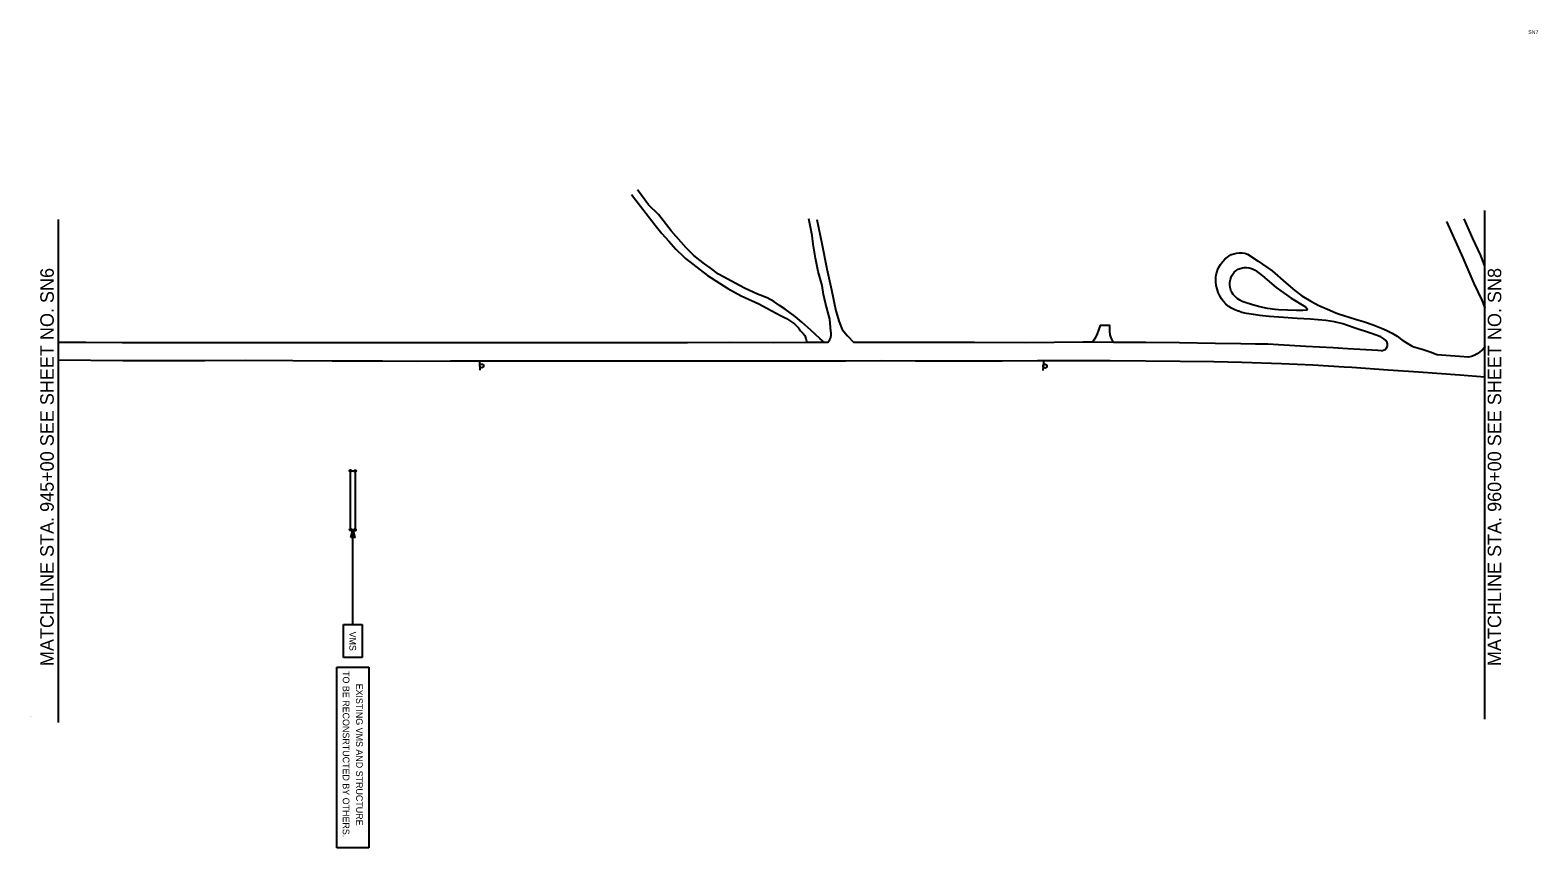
# Model space of a CAD drawing. Extents: x 1738744 to 1740329, y 1163330 to 1164190.
import ezdxf

# ---------------------------------------------------------------- set-up
doc = ezdxf.new("R2010")
doc.units = 0
for name, color, linetype in [('Default', 7, 'Continuous'), ('RD_EX_Driveway', 7, 'Continuous'), ('RD_EX_Road', 7, 'Continuous'), ('RD_SHT_MatchLine', 7, 'Continuous'), ('RD_SHT_TX', 7, 'Continuous'), ('SN_P_Signs', 7, 'Continuous')]:
    doc.layers.add(name, color=color, linetype=linetype)

msp = doc.modelspace()

# ---------------------------------------------------------------- linework, layer by layer
at = {"layer": 'RD_EX_Driveway'}
for points in [[(1739376.2, 1164017.1), (1739401, 1163985), (1739408, 1163976.3), (1739415.3, 1163968), (1739422.9, 1163959.8), (1739430.8, 1163952), (1739432.9, 1163950), (1739456.1, 1163931.9), (1739477.5, 1163918.3), (1739491.4, 1163910.8), (1739510, 1163902.2), (1739523, 1163895.2), (1739533.6, 1163889.6), (1739539, 1163886.8), (1739547.4, 1163881.2), (1739551.6, 1163876.9), (1739553.8, 1163873.8), (1739556.8, 1163871.2), (1739558.3, 1163868.9), (1739559.6, 1163865.8), (1739560.6, 1163861.5)], [(1739579.2, 1163861.6), (1739574.3, 1163865.7), (1739569.7, 1163870.1), (1739564.8, 1163874.6), (1739555.1, 1163883.1), (1739548.1, 1163888.9), (1739537.9, 1163896.8), (1739531.8, 1163900.4), (1739525.7, 1163904.6), (1739518.8, 1163908.5), (1739508.8, 1163912.5), (1739495, 1163918.6), (1739476.8, 1163928.4), (1739467.7, 1163933.6), (1739458.8, 1163940.2), (1739452.8, 1163944.3), (1739447, 1163948.8), (1739441.5, 1163953.6), (1739436.2, 1163958.6), (1739433.8, 1163961.1), (1739417.7, 1163979.1), (1739404.6, 1163996.2), (1739394.1, 1164006.4), (1739382.5, 1164022.1)], [(1739582.6, 1163861.6), (1739584.8, 1163864.8), (1739585.6, 1163867), (1739586, 1163869.3), (1739586.1, 1163871.7), (1739585.9, 1163873.1), (1739584.7, 1163886), (1739580.1, 1163902.8), (1739578.2, 1163912.2), (1739576.6, 1163921.4), (1739572.6, 1163936.3), (1739569.8, 1163950.3), (1739567.3, 1163965), (1739566, 1163974.3), (1739562.6, 1163991.5)], [(1739570.9, 1163990.8), (1739576.2, 1163965.7), (1739581.6, 1163938.9), (1739586.3, 1163917), (1739590.9, 1163895), (1739594.4, 1163883.5), (1739597.8, 1163875.2), (1739603.2, 1163868.6), (1739609.8, 1163861.6)], [(1740164.9, 1163852.8), (1740168.8, 1163854.4), (1740170.3, 1163855.9), (1740171.1, 1163857.8), (1740171.2, 1163859.7), (1740170.7, 1163861.7), (1740169.5, 1163863.6), (1740167.3, 1163865.6), (1740164, 1163867.5), (1740154.2, 1163871.2), (1740136, 1163877.2), (1740124.2, 1163881.1), (1740115.3, 1163883.4), (1740106.2, 1163884.7), (1740090.3, 1163886.1), (1740076.1, 1163887), (1740056.8, 1163888.4), (1740046.8, 1163889.1), (1740036.8, 1163890), (1740030.1, 1163890.9), (1740023, 1163892.1), (1740018.1, 1163893.3), (1740014.8, 1163894.4), (1740014, 1163894.7), (1740010.5, 1163896), (1740007.2, 1163897.6), (1740004.2, 1163899.6), (1740001.3, 1163901.9), (1739998.7, 1163904.6), (1739996.7, 1163907.4), (1739994.7, 1163910.7), (1739993.1, 1163914.2), (1739991.9, 1163917.9), (1739991.1, 1163921.7), (1739990.6, 1163925.5), (1739990.6, 1163929.3), (1739990.7, 1163930.9), (1739991, 1163932.3), (1739991.4, 1163934.3), (1739992.4, 1163937.3), (1739992.5, 1163937.6), (1739993.9, 1163940.8), (1739995.6, 1163943.8), (1739997.7, 1163946.6), (1740000.1, 1163949.2), (1740002.8, 1163951.4), (1740005.7, 1163953.3), (1740006.9, 1163954), (1740007.2, 1163954.1), (1740009.6, 1163955), (1740012.4, 1163955.7), (1740015.3, 1163956), (1740018.2, 1163955.9), (1740021.1, 1163955.4), (1740023.9, 1163954.6), (1740035.1, 1163947), (1740049.8, 1163937.1), (1740064.3, 1163924.3), (1740073.7, 1163916.4), (1740081, 1163910.6), (1740090.4, 1163905), (1740099.1, 1163900.6), (1740108, 1163896.5), (1740117, 1163892.8), (1740119.6, 1163891.8), (1740137.7, 1163886.3), (1740146.9, 1163883.5), (1740156, 1163880.3), (1740164.9, 1163876.7), (1740170.4, 1163874.2), (1740176, 1163871.4), (1740181.3, 1163868.2), (1740181.3, 1163868.1), (1740186.4, 1163864.4), (1740191.7, 1163861), (1740197.2, 1163857.9), (1740198.9, 1163857.1), (1740207.5, 1163854.6), (1740216, 1163851.7), (1740224.1, 1163848.5), (1740224.1, 1163848.5)], [(1740032, 1163937.5), (1740039.7, 1163931.7), (1740054.2, 1163919.6), (1740069.7, 1163908.2), (1740084.9, 1163899), (1740087.2, 1163896.5), (1740086.3, 1163895.6), (1740082.2, 1163895.4), (1740075.5, 1163895.2), (1740056.6, 1163895.9), (1740053, 1163896.3), (1740045, 1163897.5), (1740037, 1163899.2), (1740029.2, 1163901.2), (1740021.4, 1163903.6), (1740018.5, 1163904.6), (1740015.8, 1163906), (1740013.2, 1163907.8), (1740010.9, 1163909.9), (1740008.9, 1163912.2), (1740007.7, 1163914), (1740006.5, 1163916.6), (1740005.8, 1163919.3), (1740005.4, 1163922.1), (1740005.5, 1163924.9), (1740005.9, 1163927.7), (1740006.7, 1163930.4), (1740007.2, 1163931.5), (1740008.4, 1163933.6), (1740010, 1163935.6), (1740011.9, 1163937.2), (1740014, 1163938.6), (1740016.3, 1163939.6), (1740018.8, 1163940.3), (1740020.5, 1163940.5), (1740023.1, 1163940.5), (1740025.7, 1163940.2), (1740028.2, 1163939.5), (1740030.5, 1163938.4), (1740032, 1163937.5)], [(1739883, 1163861.7), (1739880.6, 1163866.4), (1739879.7, 1163869.7), (1739879.2, 1163873.4), (1739879.3, 1163879.4), (1739869, 1163879.5), (1739866, 1163870.6), (1739864.2, 1163867), (1739862.3, 1163864.1), (1739860.8, 1163861.8)]]:
    msp.add_lwpolyline(points, dxfattribs=at)
at = {"layer": 'RD_EX_Road'}
for points in [[(1740273.7, 1163942), (1740269.2, 1163953.2), (1740260.8, 1163971.1), (1740251.7, 1163991.7)], [(1740233.2, 1163988.7), (1740250.5, 1163950.5), (1740262.1, 1163923.6), (1740270.5, 1163906), (1740273.7, 1163898.2)], [(1739582.6, 1163861.6), (1739579.2, 1163861.6), (1739570.3, 1163861.6), (1739560.6, 1163861.5), (1739525, 1163861.4), (1739479.5, 1163861.6), (1739434.9, 1163861.4), (1739394.9, 1163861.4), (1739373.2, 1163861.4), (1739325.9, 1163861.3), (1739285, 1163861.2), (1739247, 1163861.1), (1739205.2, 1163861.3), (1739147.4, 1163861.2), (1739086.9, 1163861.1), (1739037.9, 1163861.1), (1739001, 1163861.4), (1738957.6, 1163861.4), (1738911.8, 1163861.3), (1738877.2, 1163861.4), (1738840.5, 1163861.4), (1738802.3, 1163861.5), (1738773.7, 1163861.6)], [(1740164.8, 1163852.8), (1740161, 1163853.2), (1740129.6, 1163855.1), (1740114.2, 1163855.9), (1740085.4, 1163857.3), (1740056.7, 1163859.1), (1740056.7, 1163859.1), (1740045.2, 1163859.7), (1740033.7, 1163859.9), (1740032.4, 1163859.9), (1740016.8, 1163860.2), (1739989.9, 1163860.7), (1739952.3, 1163861.2), (1739917.2, 1163861.6), (1739891.6, 1163861.7), (1739883, 1163861.7), (1739860.8, 1163861.8), (1739850.7, 1163861.8), (1739790.6, 1163861.4), (1739737, 1163861.5), (1739710.2, 1163861.5), (1739667.2, 1163861.5), (1739609.9, 1163861.6)], [(1740273.7, 1163857.3), (1740273.6, 1163857), (1740271.3, 1163854.3), (1740270.5, 1163853.5), (1740268.1, 1163851.4), (1740265.4, 1163849.6), (1740262.5, 1163848.1), (1740259.5, 1163847), (1740256.4, 1163846.3), (1740256.3, 1163846.3), (1740227.9, 1163848.3), (1740224.1, 1163848.5)], [(1740273.7, 1163825.3), (1740247.1, 1163827.2), (1740203.7, 1163830.3), (1740172, 1163832.4), (1740133.5, 1163835.3), (1740125.5, 1163835.8), (1740092.7, 1163837.8), (1740059.8, 1163839.3), (1740018, 1163840.6), (1739988.7, 1163841.4), (1739953.3, 1163841.6), (1739917.1, 1163842.1), (1739879.5, 1163842.2), (1739845.1, 1163842.2), (1739803, 1163842.3), (1739766, 1163842), (1739708.9, 1163842.1), (1739674.9, 1163842.1), (1739639, 1163842.2), (1739601.6, 1163842.1), (1739566.5, 1163842.1), (1739529.7, 1163842.1), (1739480.9, 1163842.1), (1739439.9, 1163842.1), (1739405.8, 1163842), (1739367.2, 1163841.9), (1739343.7, 1163842.1), (1739306.1, 1163842.1), (1739266.6, 1163842.1), (1739222.4, 1163842), (1739185.9, 1163842.1), (1739151.5, 1163841.8), (1739114.4, 1163841.9), (1739076.4, 1163842), (1739061.4, 1163842.1), (1739019.9, 1163842.2), (1738970.3, 1163842.6), (1738927.5, 1163842.3), (1738889.6, 1163842.5), (1738841.3, 1163842.5), (1738773.7, 1163843)]]:
    msp.add_lwpolyline(points, dxfattribs=at)
at = {"layer": 'RD_SHT_MatchLine'}
for points in [[(1738773.7, 1163461.9), (1738773.7, 1163744), (1738773.7, 1163991)], [(1740273.7, 1163465.6), (1740273.7, 1163744), (1740273.7, 1164000.3)]]:
    msp.add_lwpolyline(points, dxfattribs=at)
at = {"layer": 'SN_P_Signs'}
for p, q in [((1739216.4, 1163841.4), (1739216.8, 1163832.4)), ((1739809.3, 1163841.3), (1739808.7, 1163832.3)), ((1739079.6, 1163726.2), (1739081.4, 1163727.2)), ((1739080, 1163727.6), (1739081, 1163725.8)), ((1739084.6, 1163726), (1739086.3, 1163727)), ((1739085, 1163727.4), (1739085.9, 1163725.6)), ((1739079.9, 1163664.4), (1739081.6, 1163665.3)), ((1739080.2, 1163665.7), (1739081.2, 1163664)), ((1739083.1, 1163565.2), (1739083.1, 1163664.7)), ((1739084.6, 1163664.2), (1739086.3, 1163665.1)), ((1739085, 1163665.5), (1739085.9, 1163663.8)), ((1739073.3, 1163530.2), (1739073.3, 1163565.2)), ((1739073.3, 1163565.2), (1739092.9, 1163565.2)), ((1739092.9, 1163565.2), (1739092.9, 1163530.2)), ((1739066.3, 1163330.2), (1739066.3, 1163520.2)), ((1739066.3, 1163520.2), (1739099.9, 1163520.2)), ((1739092.9, 1163530.2), (1739073.3, 1163530.2)), ((1739099.9, 1163520.2), (1739099.9, 1163330.2)), ((1739099.9, 1163330.2), (1739066.3, 1163330.2))]:
    msp.add_line(p, q, dxfattribs=at)
for points in [[(1739080.2, 1163725.7), (1739080.1, 1163725.8), (1739079.9, 1163725.9), (1739079.8, 1163726), (1739079.7, 1163726.1), (1739079.6, 1163726.2), (1739079.5, 1163726.4), (1739079.5, 1163726.6), (1739079.5, 1163726.7), (1739079.5, 1163726.9), (1739079.6, 1163727), (1739079.7, 1163727.2), (1739079.8, 1163727.3), (1739079.9, 1163727.5), (1739080, 1163727.5), (1739080.2, 1163727.6), (1739080.3, 1163727.7), (1739080.5, 1163727.7), (1739080.7, 1163727.7), (1739080.8, 1163727.6)], [(1739080.8, 1163727.6), (1739080.9, 1163727.6), (1739081.1, 1163727.5), (1739081.2, 1163727.4), (1739081.3, 1163727.3), (1739081.4, 1163727.1), (1739081.5, 1163727), (1739081.5, 1163726.8), (1739081.5, 1163726.6), (1739081.5, 1163726.5), (1739081.4, 1163726.3), (1739081.4, 1163726.2), (1739081.3, 1163726), (1739081.1, 1163725.9), (1739081, 1163725.8), (1739080.9, 1163725.7), (1739080.7, 1163725.7), (1739080.5, 1163725.7), (1739080.4, 1163725.7), (1739080.2, 1163725.7)], [(1739080.7, 1163664.8), (1739080.5, 1163726.7), (1739085.5, 1163726.5), (1739085.4, 1163664.7), (1739080.7, 1163664.8)], [(1739085.2, 1163725.5), (1739085, 1163725.6), (1739084.9, 1163725.7), (1739084.8, 1163725.8), (1739084.6, 1163725.9), (1739084.6, 1163726), (1739084.5, 1163726.2), (1739084.5, 1163726.4), (1739084.5, 1163726.5), (1739084.5, 1163726.7), (1739084.5, 1163726.9), (1739084.6, 1163727), (1739084.7, 1163727.1), (1739084.8, 1163727.3), (1739085, 1163727.4), (1739085.1, 1163727.4), (1739085.3, 1163727.5), (1739085.4, 1163727.5), (1739085.6, 1163727.5), (1739085.7, 1163727.4)], [(1739085.7, 1163727.4), (1739085.9, 1163727.4), (1739086, 1163727.3), (1739086.2, 1163727.2), (1739086.3, 1163727.1), (1739086.4, 1163726.9), (1739086.4, 1163726.8), (1739086.5, 1163726.6), (1739086.5, 1163726.4), (1739086.4, 1163726.3), (1739086.4, 1163726.1), (1739086.3, 1163726), (1739086.2, 1163725.8), (1739086.1, 1163725.7), (1739086, 1163725.6), (1739085.8, 1163725.5), (1739085.6, 1163725.5), (1739085.5, 1163725.5), (1739085.3, 1163725.5), (1739085.2, 1163725.5)], [(1739080.4, 1163663.9), (1739080.3, 1163663.9), (1739080.1, 1163664), (1739080, 1163664.1), (1739079.9, 1163664.3), (1739079.8, 1163664.4), (1739079.8, 1163664.6), (1739079.7, 1163664.7), (1739079.7, 1163664.9), (1739079.7, 1163665.1), (1739079.8, 1163665.2), (1739079.9, 1163665.4), (1739080, 1163665.5), (1739080.1, 1163665.6), (1739080.2, 1163665.7), (1739080.4, 1163665.8), (1739080.5, 1163665.8), (1739080.7, 1163665.8), (1739080.9, 1163665.8), (1739081, 1163665.8)], [(1739081, 1163665.8), (1739081.2, 1163665.7), (1739081.3, 1163665.7), (1739081.4, 1163665.5), (1739081.5, 1163665.4), (1739081.6, 1163665.3), (1739081.7, 1163665.1), (1739081.7, 1163665), (1739081.7, 1163664.8), (1739081.7, 1163664.6), (1739081.7, 1163664.5), (1739081.6, 1163664.3), (1739081.5, 1163664.2), (1739081.4, 1163664.1), (1739081.2, 1163664), (1739081.1, 1163663.9), (1739080.9, 1163663.9), (1739080.7, 1163663.8), (1739080.6, 1163663.9), (1739080.4, 1163663.9)], [(1739085.2, 1163663.7), (1739085, 1163663.8), (1739084.9, 1163663.8), (1739084.7, 1163663.9), (1739084.6, 1163664.1), (1739084.5, 1163664.2), (1739084.5, 1163664.4), (1739084.4, 1163664.5), (1739084.4, 1163664.7), (1739084.5, 1163664.9), (1739084.5, 1163665), (1739084.6, 1163665.2), (1739084.7, 1163665.3), (1739084.8, 1163665.4), (1739084.9, 1163665.5), (1739085.1, 1163665.6), (1739085.2, 1163665.6), (1739085.4, 1163665.7), (1739085.6, 1163665.6), (1739085.7, 1163665.6)], [(1739085.7, 1163665.6), (1739085.9, 1163665.6), (1739086, 1163665.5), (1739086.1, 1163665.4), (1739086.2, 1163665.2), (1739086.3, 1163665.1), (1739086.4, 1163664.9), (1739086.4, 1163664.8), (1739086.4, 1163664.6), (1739086.4, 1163664.4), (1739086.4, 1163664.3), (1739086.3, 1163664.1), (1739086.2, 1163664), (1739086.1, 1163663.9), (1739085.9, 1163663.8), (1739085.8, 1163663.7), (1739085.6, 1163663.7), (1739085.5, 1163663.7), (1739085.3, 1163663.7), (1739085.2, 1163663.7)]]:
    msp.add_lwpolyline(points, dxfattribs=at)
msp.add_lwpolyline([(1739081, 1163656.5), (1739083.1, 1163664.7), (1739085.1, 1163656.5)], close=True, dxfattribs=at)
for centre in [(1739218.6, 1163837), (1739811, 1163836.7)]:
    msp.add_circle(centre, 2, dxfattribs=at)

# ---------------------------------------------------------------- texts
at = {"layer": 'Default'}
for s, p in [('Sheet: 7', (1738743.7, 1163468.8)), ('Angle:  16.0848', (1738743.7, 1163468.6)), ('Align: A_I85', (1738743.7, 1163468.3))]:
    msp.add_text(s, height=0.208, dxfattribs=at).set_placement(p)
at = {"layer": 'RD_SHT_TX'}
msp.add_text('SN7', height=4, dxfattribs=at).set_placement((1740319.2, 1164186))
for s, p in [('MATCHLINE STA. 945+00 SEE SHEET NO. SN6', (1738768.5, 1163521.3)), ('MATCHLINE STA. 960+00 SEE SHEET NO. SN8', (1740290.7, 1163521.3))]:
    msp.add_text(s, height=14.173, rotation=89.9856, dxfattribs=at).set_placement(p)
at = {"layer": 'SN_P_Signs'}
for s, p in [('VMS', (1739079.5, 1163557.6)), ('TO BE RECONSRTUCTED BY OTHERS.', (1739072.5, 1163516.1)), ('EXISTING VMS AND STRUCTURE', (1739086.5, 1163502.9))]:
    msp.add_text(s, height=7, rotation=270.0001, dxfattribs=at).set_placement(p)

doc.saveas('drawing.dxf')
